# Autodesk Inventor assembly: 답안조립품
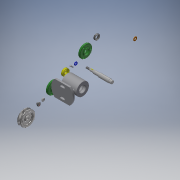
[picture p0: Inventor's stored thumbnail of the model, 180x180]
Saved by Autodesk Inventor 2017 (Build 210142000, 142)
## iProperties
Part Number: 답안조립품
Material: 일반
Document SubType Name: Assembly
Designer: 601-13
Author: 601-13
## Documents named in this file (14)
- C:\Users\601-13\Desktop\720206V1003\답안조립품.iam
- C:\Users\601-13\Desktop\720206V1003\본체.ipt
- C:\Users\601-13\Desktop\720206V1003\V벨트풀리.ipt
- C:\Users\601-13\Desktop\720206V1003\고무 캡.ipt
- C:\Users\601-13\Desktop\720206V1003\너트 M8.ipt
- C:\Users\601-13\Desktop\720206V1003\뒤커버.ipt
- C:\Users\601-13\Desktop\720206V1003\베어링 6002.ipt
- C:\Users\601-13\Desktop\720206V1003\볼트 M4 x 10.ipt
- C:\Users\601-13\Desktop\720206V1003\스프링와셔 8.ipt
- C:\Users\601-13\Desktop\720206V1003\앞커버.ipt
- C:\Users\601-13\Desktop\720206V1003\오일 실 15 x 25 x 7.ipt
- C:\Users\601-13\Desktop\720206V1003\축.ipt
- C:\Users\601-13\Desktop\720206V1003\키 3 x 3 x 12.ipt
- C:\Users\601-13\Desktop\720206V1003\평와셔 8 x 17.ipt
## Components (2 placed, 2 different names)
1. V벨트풀리:1
2. 고무 캡:1
